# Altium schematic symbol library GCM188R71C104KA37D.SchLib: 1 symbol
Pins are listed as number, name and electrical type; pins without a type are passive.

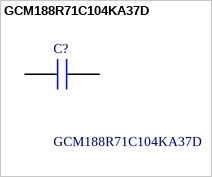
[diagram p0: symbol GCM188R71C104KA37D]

## GCM188R71C104KA37D
designator C?
Murata 100nF Multilayer Ceramic Capacitor MLCC 16V dc +/-10% X7R Dielectric 0603 (1608M) SMD, Max. Temp. +125C; Manufacturer_Name: Murata Electronics; Geometry.Height: 0.9mm
footprint CAPC1608X90N
pins: 1, 2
